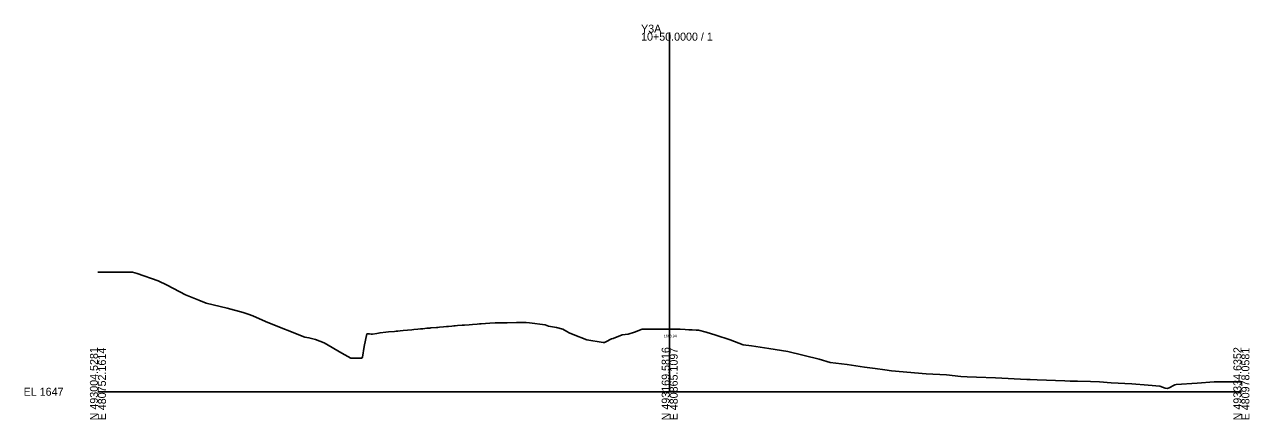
# Model space of a CAD drawing. Extents: x -26 to 403, y -10 to 3108.
# Drawn here: x -25.7 to 402.8, y 490.3 to 628.4 of the extents above; entities that cross this region are included whole.
import ezdxf

# ---------------------------------------------------------------- set-up
doc = ezdxf.new("R2010")
doc.units = 0
for name, color, linetype in [('Exist Cross Section Cell', 7, 'Continuous'), ('Exist XS Center Line Elevation Label', 7, 'Continuous'), ('Exist XS Ground Line', 7, 'Continuous')]:
    doc.layers.add(name, color=color, linetype=linetype)

msp = doc.modelspace()

# ---------------------------------------------------------------- linework, layer by layer
at = {"layer": 'Exist Cross Section Cell'}
for p, q in [((200, 500), (200, 625.57)), ((0, 500), (200, 500)), ((200, 500), (400, 500))]:
    msp.add_line(p, q, dxfattribs=at)
at = {"layer": 'Exist XS Ground Line'}
msp.add_lwpolyline([(0, 541.84), (5.06, 541.86), (6.92, 541.84), (7.22, 541.84), (12.07, 541.84), (13.7, 541.35), (21.03, 538.76), (24.27, 537.23), (30.65, 533.86), (35.26, 532.08), (37.85, 530.98), (45.24, 529.22), (50.85, 527.75), (52.51, 527.17), (54.16, 526.57), (56.51, 525.45), (59.39, 524.27), (72.38, 519.14), (73.8, 518.87), (76.14, 518.31), (79.19, 517.08), (85.29, 513.52), (88.45, 511.75), (89.8, 511.7), (90.27, 511.71), (92.3, 511.79), (92.5, 512.11), (93.11, 515.88), (94.11, 520.23), (94.95, 520.23), (95.62, 520.17), (95.99, 520.09), (97.6, 520.39), (98.67, 520.61), (100.69, 520.83), (101.68, 520.93), (103.74, 521.12), (104.33, 521.17), (104.86, 521.22), (105.73, 521.3), (106.77, 521.41), (108.31, 521.55), (109.84, 521.69), (110.54, 521.76), (111.9, 521.89), (112.8, 521.98), (113.7, 522.06), (115.04, 522.19), (115.66, 522.24), (116.13, 522.29), (116.5, 522.32), (118.38, 522.48), (118.87, 522.52), (119.43, 522.57), (120.93, 522.71), (121.93, 522.8), (122.69, 522.87), (123.81, 522.97), (124.5, 523.04), (124.95, 523.08), (125.76, 523.14), (127.41, 523.29), (128.18, 523.34), (129.9, 523.46), (131.01, 523.54), (132.65, 523.65), (133.45, 523.7), (134.01, 523.73), (137.05, 523.94), (138.91, 524.06), (140.09, 524.11), (140.82, 524.14), (142.03, 524.15), (142.51, 524.15), (143.15, 524.15), (146.38, 524.17), (147.92, 524.18), (148.27, 524.18), (149.16, 524.18), (149.8, 524.21), (150.98, 524.06), (156.4, 523.39), (157.64, 522.97), (160.44, 522.42), (162.58, 521.93), (164.01, 521.09), (164.79, 520.57), (166.23, 519.97), (170.98, 518.18), (176.74, 517.27), (177.22, 517.18), (177.7, 517.43), (179.71, 518.47), (180.22, 518.66), (183.43, 519.88), (185.45, 520.19), (187.67, 520.79), (190.42, 521.84), (191.02, 521.85), (191.69, 521.87), (194.67, 521.91), (197.67, 521.93), (198.24, 521.93), (200.12, 521.94), (200.68, 521.94), (203.71, 521.84), (205.42, 521.76), (206.76, 521.69), (207.89, 521.63), (209.25, 521.57), (210.14, 521.5), (212.81, 520.82), (216.13, 519.83), (221.19, 518.11), (225.66, 516.46), (228.58, 516.09), (234.73, 515.15), (241.29, 514.08), (252.3, 511.41), (256.1, 510.27), (262.04, 509.51), (268.11, 508.65), (271.87, 508.11), (275.3, 507.64), (277.65, 507.32), (289.77, 506.32), (296.89, 505.95), (301.89, 505.37), (304.08, 505.19), (307.29, 505.13), (314.01, 504.93), (325, 504.33), (326.13, 504.26), (328.57, 504.18), (338.25, 503.78), (340.06, 503.74), (342.71, 503.69), (347.26, 503.55), (350.37, 503.46), (354.45, 503.15), (361.73, 502.74), (367.41, 502.32), (371.44, 501.95), (373.34, 501.29), (374.06, 501.12), (374.75, 501.38), (376.44, 502.31), (376.75, 502.45), (377.24, 502.49), (384.51, 502.98), (390.43, 503.49), (395.84, 503.43), (398.85, 503.44), (400, 503.51)], dxfattribs=at)

# ---------------------------------------------------------------- texts
at = {"layer": 'Exist Cross Section Cell'}
for s, p in [('Y3A', (190, 625.57)), ('10+50.0000 / 1', (190, 622.77)), ('EL 1647', (-26, 498.6))]:
    msp.add_text(s, height=2.8, dxfattribs=at).set_placement(p)
for s, p in [('N 493004.5281', (0, 490)), ('E 480752.1614', (2.8, 490)), ('N 493169.5816', (200, 490)), ('E 480865.1097', (202.8, 490)), ('N 493334.6352', (400, 490)), ('E 480978.0581', (402.8, 490))]:
    msp.add_text(s, height=2.8, rotation=90, dxfattribs=at).set_placement(p)
at = {"layer": 'Exist XS Center Line Elevation Label'}
msp.add_text('1668.94', height=0.9, dxfattribs=at).set_placement((197.94, 519.04))

doc.saveas('drawing.dxf')
